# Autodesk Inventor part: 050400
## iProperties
Shininess: 69.0
Length Units: 11269
Angle Units: 11279
Time Units: 11290
Mass Units: 11284
Length Display Precision: 3
Angle Display Precision: 2
Compacted: True
Company: Pneumax S.p.A.
Part Number: 050400
Material: Default
Description: T INNESTABILE Ø4
Document SubType Name: Modellazione
Catalog Web Link: www.pneumaxspa.com
Density: 1.59
Volumn: 0.8648857994912436
Area: 17.092995283760587
PropertySet Name: Model Information
Control State: 0
Master: False
Checked Out: False
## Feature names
1. Revolution6
2. Serie circolare3 [Circular Pattern]
3. Circular Pattern7
4. Foro6 [Hole]
5. Serie circolare6 [Circular Pattern]
